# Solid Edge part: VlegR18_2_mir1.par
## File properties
Author: Türk
Template: Iso Part.par
Last saved by: Türk
Revision: 2
Application: Solid Edge
Accuracy: 0,990
Username: Türk
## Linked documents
VlegR18_2.par
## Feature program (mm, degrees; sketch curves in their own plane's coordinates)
part copy "CopiedPart_1"
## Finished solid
Body 1: solid body, 140 faces, 339 edges, 182 vertices, 2 internal voids.
  Faces by surface: cylinder 65, plane 24, torus 23, blend 14, cone 9, spun 5
  Edges by curve: intersection 145, circle 130, line 64
Bounding box of the edges (mm; curved faces can reach further): 200.000 x 457.200 x 457.200, from (-100, -228.6, -228.6) to (100, 228.6, 228.6).
Cylindrical faces by radius (mm): R4 x16, R6 x5, R15 x5, R25 x16, R62.5 x1, R80 x8, R174.2298 x8, R203.6 x2, R216.1 x2, R228.6 x2
Conical faces (half-angle, radius in mm at the cone's reference point): 2.0106 deg R178.4522 x2, 5.4632 deg R201.6202 x2, 54.824 deg R174.2298 x1, 54.824 deg R203.0605 x2, 54.824 deg R203.6 x1, 83.4677 deg R62.5 x1
Toroidal faces (ring radius, tube radius in mm): R79 r1 x7, R136.945 r40 x8, R205.6 r2 x2, R214.1 r2 x2, R226.6 r2 x4
Planar faces by outward normal: +x 4, -x 4, oblique 16
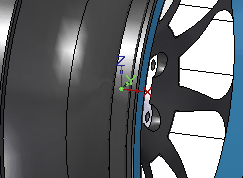
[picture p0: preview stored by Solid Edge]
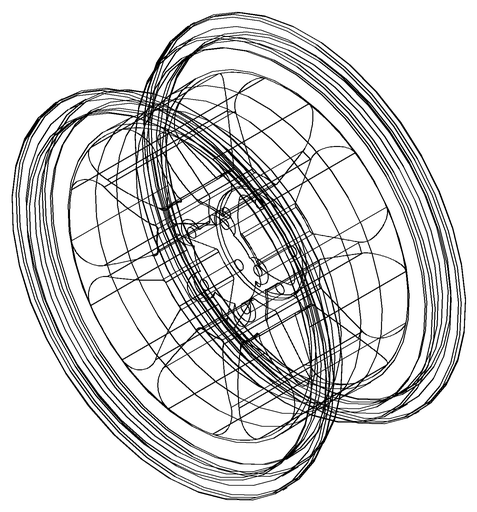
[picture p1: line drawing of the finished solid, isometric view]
